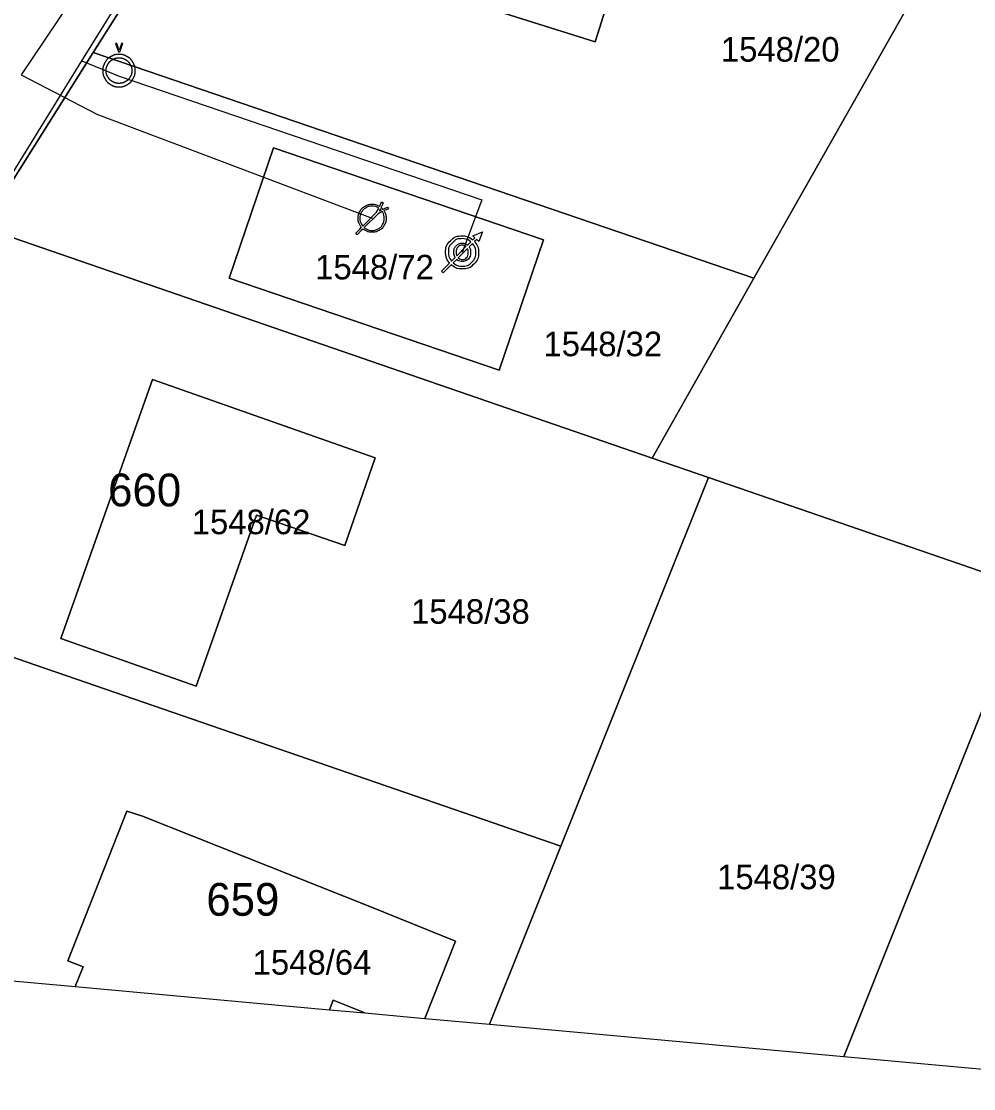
# Model space of a CAD drawing. Extents: x -559813 to -559493, y -1075874 to -1075701.
# Drawn here: x -559709.6 to -559651.4, y -1075862.6 to -1075797.4 of the extents above; entities that cross this region are included whole.
import ezdxf

# ---------------------------------------------------------------- set-up
doc = ezdxf.new("R2010")
doc.units = 0
for name, color, linetype in [('Adresní místo-text', 7, 'Continuous'), ('Default', 7, 'Continuous'), ('Kanalizační přípojka', 7, 'Continuous'), ('Kanalizační stoka', 7, 'Continuous'), ('Odběrné místo', 7, 'Continuous'), ('Odběrné místo na kanalizaci', 7, 'Continuous'), ('Parcela-polygon', 7, 'Continuous'), ('Parcela-text', 7, 'Continuous'), ('Vodovodní přípojka', 7, 'Continuous'), ('Vodovodní řad', 7, 'Continuous'), ('Vodovodní šachta', 7, 'Continuous')]:
    doc.layers.add(name, color=color, linetype=linetype)

msp = doc.modelspace()

# ---------------------------------------------------------------- linework, layer by layer
at = {"layer": 'Default'}
for points, degree in [([(-559704.154, -1075799.528), (-559704.311, -1075799.612), (-559704.434, -1075799.734), (-559704.523, -1075799.894)], 2), ([(-559703.669, -1075799.401), (-559703.835, -1075799.401), (-559703.997, -1075799.444), (-559704.154, -1075799.528)], 2), ([(-559704.05, -1075799.711), (-559703.926, -1075799.643), (-559703.799, -1075799.61), (-559703.669, -1075799.61)], 2), ([(-559703.658, -1075799.125), (-559703.661, -1075799.106), (-559703.664, -1075799.095), (-559703.669, -1075799.09)], 2), ([(-559703.182, -1075799.528), (-559703.34, -1075799.444), (-559703.502, -1075799.401), (-559703.669, -1075799.401)], 2), ([(-559703.669, -1075799.61), (-559703.536, -1075799.61), (-559703.408, -1075799.643), (-559703.284, -1075799.711)], 2), ([(-559703.645, -1075799.09), (-559703.649, -1075799.099), (-559703.654, -1075799.111), (-559703.658, -1075799.125)], 2), ([(-559702.811, -1075799.894), (-559702.9, -1075799.734), (-559703.023, -1075799.612), (-559703.182, -1075799.528)], 2), ([(-559704.523, -1075799.894), (-559704.612, -1075800.053), (-559704.656, -1075800.219), (-559704.656, -1075800.393)], 2), ([(-559704.448, -1075800.393), (-559704.448, -1075800.256), (-559704.413, -1075800.125), (-559704.342, -1075800)], 2), ([(-559704.342, -1075800), (-559704.271, -1075799.874), (-559704.174, -1075799.778), (-559704.05, -1075799.711)], 2), ([(-559703.284, -1075799.711), (-559703.16, -1075799.778), (-559703.063, -1075799.874), (-559702.992, -1075800)], 2), ([(-559702.992, -1075800), (-559702.921, -1075800.125), (-559702.886, -1075800.256), (-559702.886, -1075800.393)], 2), ([(-559702.677, -1075800.393), (-559702.677, -1075800.219), (-559702.722, -1075800.053), (-559702.811, -1075799.894)], 2), ([(-559704.656, -1075800.393), (-559704.656, -1075800.563), (-559704.613, -1075800.727), (-559704.525, -1075800.883)], 2), ([(-559704.525, -1075800.883), (-559704.437, -1075801.039), (-559704.315, -1075801.161), (-559704.157, -1075801.249)], 2), ([(-559704.344, -1075800.779), (-559704.413, -1075800.656), (-559704.448, -1075800.527), (-559704.448, -1075800.393)], 2), ([(-559704.055, -1075801.066), (-559704.178, -1075800.998), (-559704.274, -1075800.902), (-559704.344, -1075800.779)], 2), ([(-559702.99, -1075800.779), (-559703.06, -1075800.902), (-559703.156, -1075800.998), (-559703.279, -1075801.066)], 2), ([(-559703.173, -1075801.249), (-559703.016, -1075801.161), (-559702.894, -1075801.039), (-559702.807, -1075800.883)], 2), ([(-559702.886, -1075800.393), (-559702.886, -1075800.527), (-559702.921, -1075800.656), (-559702.99, -1075800.779)], 2), ([(-559702.807, -1075800.883), (-559702.721, -1075800.727), (-559702.677, -1075800.563), (-559702.677, -1075800.393)], 2), ([(-559704.157, -1075801.249), (-559704, -1075801.337), (-559703.837, -1075801.38), (-559703.669, -1075801.38)], 2), ([(-559703.669, -1075801.168), (-559703.803, -1075801.168), (-559703.932, -1075801.134), (-559704.055, -1075801.066)], 2), ([(-559703.279, -1075801.066), (-559703.402, -1075801.134), (-559703.532, -1075801.168), (-559703.669, -1075801.168)], 2), ([(-559703.669, -1075801.38), (-559703.495, -1075801.38), (-559703.33, -1075801.337), (-559703.173, -1075801.249)], 2), ([(-559688.85, -1075809.968), (-559688.902, -1075809.907), (-559688.942, -1075809.833), (-559689.055, -1075809.63), (-559689.055, -1075809.408), (-559689.055, -1075809.185), (-559688.94, -1075808.979), (-559688.826, -1075808.774), (-559688.621, -1075808.663), (-559688.417, -1075808.553), (-559688.201, -1075808.553), (-559687.986, -1075808.553), (-559687.782, -1075808.663), (-559687.762, -1075808.674), (-559687.744, -1075808.686)], 3), ([(-559687.794, -1075808.786), (-559687.815, -1075808.773), (-559687.836, -1075808.761), (-559688.014, -1075808.665), (-559688.201, -1075808.665), (-559688.388, -1075808.665), (-559688.566, -1075808.761), (-559688.744, -1075808.857), (-559688.843, -1075809.036), (-559688.943, -1075809.214), (-559688.943, -1075809.408), (-559688.943, -1075809.601), (-559688.844, -1075809.777), (-559688.812, -1075809.836), (-559688.769, -1075809.887)], 3), ([(-559687.649, -1075808.753), (-559687.593, -1075808.799), (-559687.546, -1075808.856)], 2), ([(-559687.48, -1075808.949), (-559687.471, -1075808.963), (-559687.461, -1075808.979), (-559687.346, -1075809.185), (-559687.346, -1075809.408), (-559687.346, -1075809.63), (-559687.459, -1075809.833), (-559687.572, -1075810.037), (-559687.775, -1075810.149), (-559687.979, -1075810.262), (-559688.201, -1075810.262), (-559688.422, -1075810.262), (-559688.625, -1075810.149), (-559688.7, -1075810.109), (-559688.762, -1075810.056)], 3), ([(-559688.681, -1075809.975), (-559688.63, -1075810.018), (-559688.57, -1075810.051), (-559688.393, -1075810.15), (-559688.201, -1075810.15), (-559688.008, -1075810.15), (-559687.831, -1075810.052), (-559687.655, -1075809.954), (-559687.557, -1075809.777), (-559687.458, -1075809.601), (-559687.458, -1075809.408), (-559687.458, -1075809.214), (-559687.558, -1075809.036), (-559687.569, -1075809.017), (-559687.579, -1075809)], 3), ([(-559687.65, -1075808.907), (-559687.674, -1075808.88), (-559687.7, -1075808.857)], 2), ([(-559683.469, -1075812.145), (-559683.709, -1075811.868), (-559683.709, -1075811.492), (-559683.709, -1075811.074), (-559683.414, -1075810.779), (-559683.118, -1075810.485), (-559682.7, -1075810.485), (-559682.325, -1075810.485), (-559682.049, -1075810.721)], 3), ([(-559682.167, -1075810.841), (-559682.394, -1075810.652), (-559682.7, -1075810.652), (-559683.049, -1075810.652), (-559683.295, -1075810.898), (-559683.541, -1075811.144), (-559683.541, -1075811.492), (-559683.541, -1075811.798), (-559683.349, -1075812.025)], 3), ([(-559681.941, -1075810.828), (-559681.691, -1075811.108), (-559681.691, -1075811.492), (-559681.691, -1075811.909), (-559681.987, -1075812.204), (-559682.282, -1075812.499), (-559682.7, -1075812.499), (-559683.083, -1075812.499), (-559683.362, -1075812.252)], 3), ([(-559683.243, -1075812.133), (-559683.013, -1075812.33), (-559682.7, -1075812.33), (-559682.352, -1075812.33), (-559682.105, -1075812.085), (-559681.858, -1075811.84), (-559681.858, -1075811.492), (-559681.858, -1075811.178), (-559682.06, -1075810.947)], 3), ([(-559683.129, -1075811.804), (-559683.138, -1075811.788), (-559683.145, -1075811.772), (-559683.207, -1075811.645), (-559683.207, -1075811.504), (-559683.207, -1075811.237), (-559683.063, -1075811.085), (-559682.919, -1075810.934), (-559682.692, -1075810.934), (-559682.545, -1075810.934), (-559682.425, -1075811.005), (-559682.396, -1075811.023), (-559682.37, -1075811.044)], 3), ([(-559682.464, -1075811.138), (-559682.481, -1075811.123), (-559682.501, -1075811.111), (-559682.586, -1075811.057), (-559682.692, -1075811.057), (-559682.842, -1075811.057), (-559682.952, -1075811.16), (-559683.061, -1075811.263), (-559683.061, -1075811.506), (-559683.061, -1075811.617), (-559683.027, -1075811.702)], 3), ([(-559682.269, -1075811.156), (-559682.254, -1075811.179), (-559682.242, -1075811.204), (-559682.18, -1075811.331), (-559682.18, -1075811.492), (-559682.18, -1075811.655), (-559682.245, -1075811.784), (-559682.311, -1075811.913), (-559682.432, -1075811.979), (-559682.553, -1075812.046), (-559682.693, -1075812.046), (-559682.845, -1075812.046), (-559682.964, -1075811.973), (-559683.001, -1075811.949), (-559683.033, -1075811.923)], 3), ([(-559682.94, -1075811.829), (-559682.84, -1075811.924), (-559682.695, -1075811.924), (-559682.534, -1075811.924), (-559682.43, -1075811.811), (-559682.326, -1075811.698), (-559682.326, -1075811.49), (-559682.326, -1075811.36), (-559682.37, -1075811.262), (-559682.371, -1075811.261), (-559682.371, -1075811.26)], 3)]:
    msp.add_open_spline(points, degree=degree, dxfattribs=at)
at = {"layer": 'Kanalizační přípojka'}
msp.add_lwpolyline([(-559709.634, -1075800.651), (-559705.016, -1075803.04), (-559688.201, -1075809.408)], dxfattribs=at)
at = {"layer": 'Kanalizační stoka'}
msp.add_lwpolyline([(-559704.486, -1075792.979), (-559709.634, -1075800.651)], dxfattribs=at)
at = {"layer": 'Odběrné místo'}
for points in [[(-559682.049, -1075810.721), (-559681.921, -1075810.593)], [(-559681.921, -1075810.593), (-559682.039, -1075810.482), (-559681.452, -1075810.242), (-559681.674, -1075810.828), (-559681.811, -1075810.698), (-559681.941, -1075810.828)], [(-559683.027, -1075811.702), (-559682.464, -1075811.138)], [(-559682.371, -1075811.26), (-559682.94, -1075811.829)], [(-559682.37, -1075811.044), (-559682.167, -1075810.841)], [(-559682.06, -1075810.947), (-559682.269, -1075811.156)], [(-559683.349, -1075812.025), (-559683.129, -1075811.804)], [(-559683.033, -1075811.923), (-559683.243, -1075812.133)], [(-559683.362, -1075812.252), (-559683.851, -1075812.742), (-559683.952, -1075812.629), (-559683.469, -1075812.145)]]:
    msp.add_lwpolyline(points, dxfattribs=at)
at = {"layer": 'Odběrné místo na kanalizaci'}
for points in [[(-559687.744, -1075808.686), (-559687.734, -1075808.667), (-559687.688, -1075808.549), (-559687.627, -1075808.408), (-559687.527, -1075808.454), (-559687.592, -1075808.615), (-559687.64, -1075808.735), (-559687.649, -1075808.753)], [(-559687.546, -1075808.856), (-559687.529, -1075808.847), (-559687.408, -1075808.799), (-559687.257, -1075808.738), (-559687.202, -1075808.832), (-559687.343, -1075808.894), (-559687.461, -1075808.939), (-559687.48, -1075808.949)], [(-559688.769, -1075809.887), (-559687.926, -1075809.043), (-559687.794, -1075808.786)], [(-559687.579, -1075809), (-559687.84, -1075809.134), (-559688.681, -1075809.975)], [(-559687.7, -1075808.857), (-559687.748, -1075808.955), (-559687.65, -1075808.907)], [(-559688.762, -1075810.056), (-559688.774, -1075810.068), (-559688.864, -1075810.158), (-559689.116, -1075810.409), (-559689.203, -1075810.32), (-559688.952, -1075810.069), (-559688.862, -1075809.98), (-559688.85, -1075809.968)]]:
    msp.add_lwpolyline(points, dxfattribs=at)
at = {"layer": 'Parcela-polygon'}
for p, q in [((-559726.935, -1075854.457), (-559706.34, -1075856.328)), ((-559706.34, -1075856.328), (-559690.811, -1075857.739)), ((-559690.811, -1075857.739), (-559688.641, -1075857.936)), ((-559688.641, -1075857.936), (-559684.971, -1075858.27)), ((-559684.971, -1075858.27), (-559681.019, -1075858.629)), ((-559681.019, -1075858.629), (-559659.387, -1075860.594)), ((-559659.387, -1075860.594), (-559637.748, -1075862.56))]:
    msp.add_line(p, q, dxfattribs=at)
for points in [[(-559732.551, -1075853.947), (-559730.31, -1075847.37), (-559722.94, -1075831.81), (-559714.46, -1075813.89), (-559711.98, -1075809.97), (-559705.24, -1075799.29), (-559698.1, -1075787.99), (-559694.39, -1075782.11), (-559686.19, -1075769.14), (-559684.4, -1075766.45), (-559674.88, -1075752.15), (-559667.58, -1075740.58), (-559681.23, -1075754.03), (-559700.36, -1075780.95), (-559706.7, -1075791.01), (-559714.26, -1075803.02), (-559717.12, -1075807.32), (-559718.54, -1075809.9), (-559722.85, -1075819.18), (-559731.69, -1075838.23), (-559734.91, -1075845.17), (-559738.719, -1075853.386)], [(-559659.387, -1075860.594), (-559647.96, -1075832.01), (-559667.64, -1075825.24), (-559676.66, -1075847.75), (-559681.019, -1075858.629)], [(-559681.019, -1075858.629), (-559676.66, -1075847.75), (-559722.94, -1075831.81), (-559730.31, -1075847.37), (-559726.935, -1075854.457)], [(-559637.748, -1075862.56), (-559628.25, -1075838.8), (-559633.27, -1075837.07), (-559647.96, -1075832.01), (-559659.387, -1075860.594)], [(-559706.34, -1075856.328), (-559705.86, -1075855.12), (-559706.79, -1075854.76), (-559703.18, -1075845.61), (-559702.24, -1075845.91), (-559688.33, -1075851.43), (-559683.1, -1075853.55), (-559684.971, -1075858.27)], [(-559684.971, -1075858.27), (-559683.1, -1075853.55), (-559688.33, -1075851.43), (-559702.24, -1075845.91), (-559703.18, -1075845.61), (-559706.79, -1075854.76), (-559705.86, -1075855.12), (-559706.34, -1075856.328)], [(-559688.641, -1075857.936), (-559690.58, -1075857.16), (-559690.811, -1075857.739)], [(-559690.811, -1075857.739), (-559690.58, -1075857.16), (-559688.641, -1075857.936)]]:
    msp.add_lwpolyline(points, dxfattribs=at)
for points in [[(-559694.39, -1075782.11), (-559698.1, -1075787.99), (-559705.24, -1075799.29), (-559664.87, -1075813.06), (-559652.44, -1075791.1), (-559686.48, -1075778.75), (-559691, -1075779.13)], [(-559674.57, -1075798.64), (-559683.2, -1075795.91), (-559681, -1075788.94), (-559678.14, -1075789.85), (-559677.76, -1075788.63), (-559674.86, -1075789.55), (-559675.24, -1075790.76), (-559672.37, -1075791.67)], [(-559677.76, -1075788.63), (-559678.14, -1075789.85), (-559681, -1075788.94), (-559683.2, -1075795.91), (-559674.57, -1075798.64), (-559672.37, -1075791.67), (-559675.24, -1075790.76), (-559674.86, -1075789.55)], [(-559664.87, -1075813.06), (-559671.09, -1075824.05), (-559667.64, -1075825.24), (-559647.96, -1075832.01), (-559633.27, -1075837.07), (-559615.97, -1075804.33), (-559652.44, -1075791.1)], [(-559705.24, -1075799.29), (-559711.98, -1075809.97), (-559671.09, -1075824.05), (-559664.87, -1075813.06)], [(-559696.93, -1075813.07), (-559694.22, -1075805.1), (-559677.73, -1075810.72), (-559680.44, -1075818.69)], [(-559696.93, -1075813.07), (-559680.44, -1075818.69), (-559677.73, -1075810.72), (-559694.22, -1075805.1)], [(-559671.09, -1075824.05), (-559711.98, -1075809.97), (-559714.46, -1075813.89), (-559722.94, -1075831.81), (-559676.66, -1075847.75), (-559667.64, -1075825.24)], [(-559688.02, -1075824.03), (-559689.86, -1075829.39), (-559695.26, -1075827.53), (-559698.96, -1075837.98), (-559707.21, -1075835.07), (-559701.61, -1075819.25)], [(-559701.61, -1075819.25), (-559707.21, -1075835.07), (-559698.96, -1075837.98), (-559695.26, -1075827.53), (-559689.86, -1075829.39), (-559688.02, -1075824.03)]]:
    msp.add_lwpolyline(points, close=True, dxfattribs=at)
at = {"layer": 'Vodovodní přípojka'}
msp.add_lwpolyline([(-559705.929, -1075799.792), (-559703.666, -1075800.724), (-559681.487, -1075808.288), (-559682.702, -1075811.492)], dxfattribs=at)
at = {"layer": 'Vodovodní řad'}
msp.add_lwpolyline([(-559729.772, -1075854.199), (-559728.25, -1075842.1), (-559720.18, -1075825.84), (-559712.5, -1075810.39), (-559705.929, -1075799.792), (-559700.67, -1075791.31), (-559699.27, -1075788.8), (-559687.46, -1075770.86), (-559674.63, -1075751.91), (-559671.48, -1075746.759)], dxfattribs=at)
at = {"layer": 'Vodovodní šachta'}
for points in [[(-559703.669, -1075799.09), (-559703.792, -1075798.731), (-559703.887, -1075798.731), (-559703.693, -1075799.234)], [(-559703.693, -1075799.234), (-559703.624, -1075799.234), (-559703.426, -1075798.731), (-559703.515, -1075798.731), (-559703.645, -1075799.09)]]:
    msp.add_lwpolyline(points, dxfattribs=at)

# ---------------------------------------------------------------- texts
at = {"layer": 'Adresní místo-text'}
for s, p in [('660', (-559704.33, -1075827)), ('659', (-559698.33, -1075852))]:
    msp.add_text(s, height=2, dxfattribs=at).set_placement(p)
at = {"layer": 'Parcela-text'}
for s, p in [('1548/20', (-559666.89, -1075799.84)), ('1548/72', (-559691.68, -1075813.14)), ('1548/32', (-559677.73, -1075817.83)), ('1548/62', (-559699.22, -1075828.7)), ('1548/38', (-559685.82, -1075834.17)), ('1548/39', (-559667.12, -1075850.38)), ('1548/64', (-559695.5, -1075855.6))]:
    msp.add_text(s, height=1.5, dxfattribs=at).set_placement(p)

doc.saveas('drawing.dxf')
